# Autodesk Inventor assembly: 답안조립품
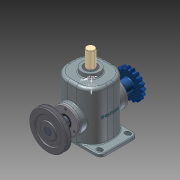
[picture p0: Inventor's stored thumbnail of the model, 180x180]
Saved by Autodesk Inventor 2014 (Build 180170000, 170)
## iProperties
Created: 2014-12
Part Number: 답안조립품
Document SubType Name: Assembly
Designer: basic
Author: basic
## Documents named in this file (15)
- C:\Users\basic\Desktop\341208V1039\답안조립품.iam
- C:\Users\basic\Desktop\341208V1039\본체.ipt
- C:\Users\basic\Desktop\341208V1039\부시.ipt
- C:\Users\basic\Desktop\341208V1039\편심축.ipt
- C:\Users\basic\Desktop\341208V1039\커버.ipt
- C:\Users\basic\Desktop\341208V1039\베어링 6205.ipt
- C:\Users\basic\Desktop\341208V1039\오일실.ipt
- C:\Users\basic\Desktop\341208V1039\키 8x8.ipt
- C:\Users\basic\Desktop\341208V1039\V-벨트풀리.ipt
- C:\Users\basic\Desktop\341208V1039\멈춤나사 M5x0.5.ipt
- C:\Users\basic\Desktop\341208V1039\체인 스프로킷.ipt
- C:\Users\basic\Desktop\341208V1039\M4x0.5.ipt
- C:\Users\basic\Desktop\341208V1039\슬라이드.ipt
- C:\Users\basic\Desktop\341208V1039\스프링 - [가변].ipt
- C:\Users\basic\Desktop\341208V1039\멈춤링.ipt
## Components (8 placed, 3 different names)
1. V-벨트풀리:1
2. 5-체인 스프로킷:1
3. M4x0.5:1
4. M4x0.5:2
5. M4x0.5:3
6. M4x0.5:4
7. M4x0.5:5
8. M4x0.5:6
